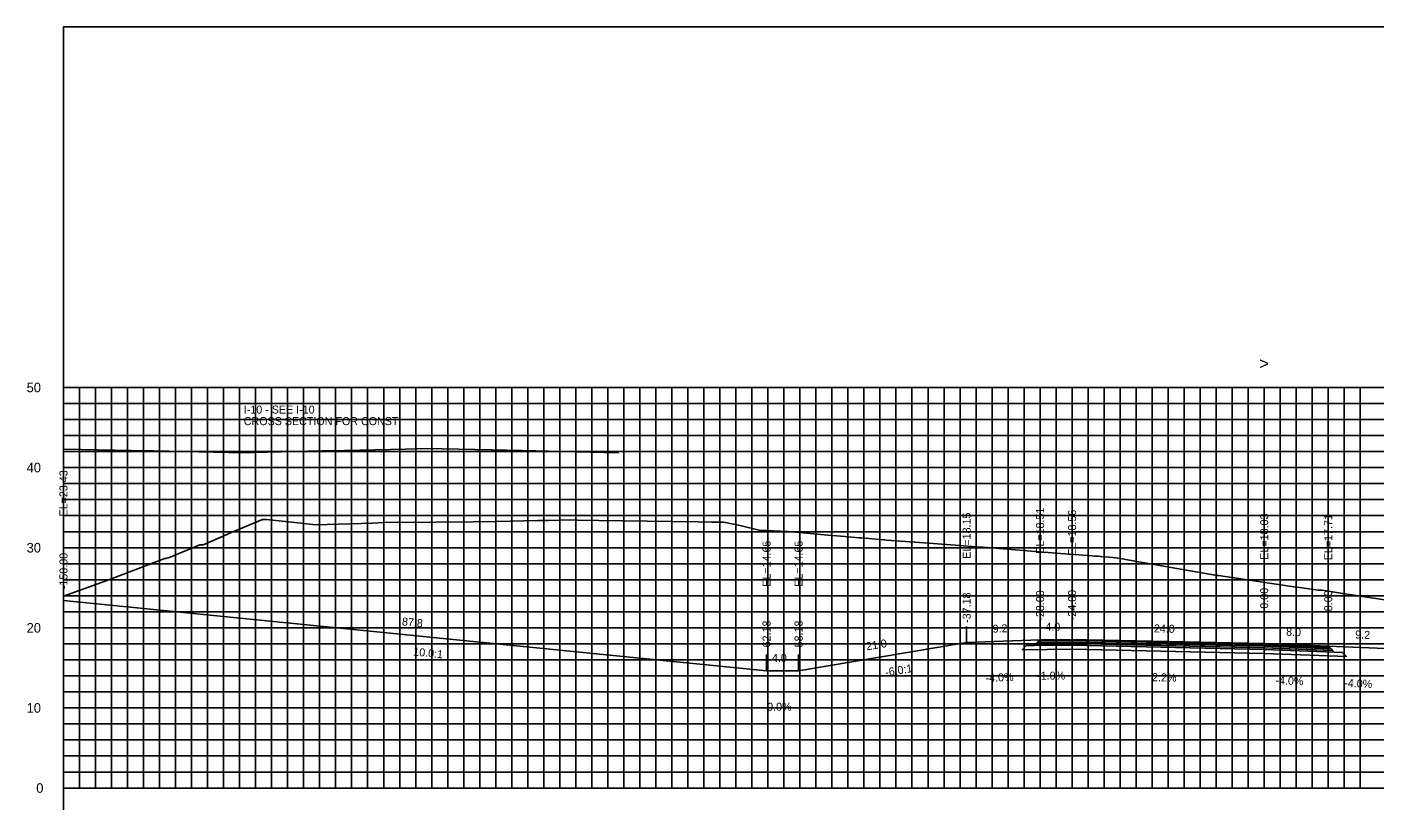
# Model space of a CAD drawing. Extents: x 1797305 to 1804485, y 245831 to 250849.
# Drawn here: x 1802476.4 to 1802644.7, y 250172.9 to 250269.4 of the extents above; entities that cross this region are included whole.
import ezdxf

# ---------------------------------------------------------------- set-up
doc = ezdxf.new("R2010")
doc.units = 0
for name, color, linetype in [('29', 7, 'Continuous'), ('60', 7, 'Continuous'), ('ALIGN-CARP', 7, 'Continuous'), ('BASE', 7, 'Continuous'), ('CL-CNST', 7, 'Continuous'), ('Level 31', 7, 'Continuous'), ('Level 62', 7, 'Continuous'), ('LIMT-CSLINE', 7, 'Continuous'), ('M-ROADS', 7, 'Continuous'), ('SURVEY - DRAINAGE - Area Shapes', 7, 'Continuous'), ('SURVEY - DRAINAGE - Bridge Hydraulic Data - Points - Locators', 7, 'Continuous')]:
    doc.layers.add(name, color=color, linetype=linetype)

msp = doc.modelspace()

# ---------------------------------------------------------------- linework, layer by layer
for p, q in [((1802481, 250197.86), (1802481, 250199.86)), ((1802593.83, 250192.58), (1802593.83, 250194.58)), ((1802603, 250192.95), (1802603, 250194.95)), ((1802607, 250192.99), (1802607, 250194.99)), ((1802631, 250192.46), (1802631, 250194.46)), ((1802639, 250192.14), (1802639, 250194.14)), ((1802568.83, 250189.08), (1802568.83, 250191.08)), ((1802572.83, 250189.08), (1802572.83, 250191.08))]:
    msp.add_line(p, q)
msp.add_lwpolyline([(1802481, 250079.43), (1802781, 250079.43), (1802781, 250269.43), (1802481, 250269.43)], close=True)
at = {"layer": '29'}
for p, q in [((1802481, 250224.43), (1802781, 250224.43)), ((1802481, 250174.43), (1802481, 250224.43)), ((1802483, 250174.43), (1802483, 250224.43)), ((1802485, 250174.43), (1802485, 250224.43)), ((1802487, 250174.43), (1802487, 250224.43)), ((1802489, 250174.43), (1802489, 250224.43)), ((1802491, 250174.43), (1802491, 250224.43)), ((1802493, 250174.43), (1802493, 250224.43)), ((1802495, 250174.43), (1802495, 250224.43)), ((1802497, 250174.43), (1802497, 250224.43)), ((1802499, 250174.43), (1802499, 250224.43)), ((1802501, 250174.43), (1802501, 250224.43)), ((1802503, 250174.43), (1802503, 250224.43)), ((1802505, 250174.43), (1802505, 250224.43)), ((1802507, 250174.43), (1802507, 250224.43)), ((1802509, 250174.43), (1802509, 250224.43)), ((1802511, 250174.43), (1802511, 250224.43)), ((1802513, 250174.43), (1802513, 250224.43)), ((1802515, 250174.43), (1802515, 250224.43)), ((1802517, 250174.43), (1802517, 250224.43)), ((1802519, 250174.43), (1802519, 250224.43)), ((1802521, 250174.43), (1802521, 250224.43)), ((1802523, 250174.43), (1802523, 250224.43)), ((1802525, 250174.43), (1802525, 250224.43)), ((1802527, 250174.43), (1802527, 250224.43)), ((1802529, 250174.43), (1802529, 250224.43)), ((1802531, 250174.43), (1802531, 250224.43)), ((1802533, 250174.43), (1802533, 250224.43)), ((1802535, 250174.43), (1802535, 250224.43)), ((1802537, 250174.43), (1802537, 250224.43)), ((1802539, 250174.43), (1802539, 250224.43)), ((1802541, 250174.43), (1802541, 250224.43)), ((1802543, 250174.43), (1802543, 250224.43)), ((1802545, 250174.43), (1802545, 250224.43)), ((1802547, 250174.43), (1802547, 250224.43)), ((1802549, 250174.43), (1802549, 250224.43)), ((1802551, 250174.43), (1802551, 250224.43)), ((1802553, 250174.43), (1802553, 250224.43)), ((1802555, 250174.43), (1802555, 250224.43)), ((1802557, 250174.43), (1802557, 250224.43)), ((1802559, 250174.43), (1802559, 250224.43)), ((1802561, 250174.43), (1802561, 250224.43)), ((1802563, 250174.43), (1802563, 250224.43)), ((1802565, 250174.43), (1802565, 250224.43)), ((1802567, 250174.43), (1802567, 250224.43)), ((1802569, 250174.43), (1802569, 250224.43)), ((1802571, 250174.43), (1802571, 250224.43)), ((1802573, 250174.43), (1802573, 250224.43)), ((1802575, 250174.43), (1802575, 250224.43)), ((1802577, 250174.43), (1802577, 250224.43)), ((1802579, 250174.43), (1802579, 250224.43)), ((1802581, 250174.43), (1802581, 250224.43)), ((1802583, 250174.43), (1802583, 250224.43)), ((1802585, 250174.43), (1802585, 250224.43)), ((1802587, 250174.43), (1802587, 250224.43)), ((1802589, 250174.43), (1802589, 250224.43)), ((1802591, 250174.43), (1802591, 250224.43)), ((1802593, 250174.43), (1802593, 250224.43)), ((1802595, 250174.43), (1802595, 250224.43)), ((1802597, 250174.43), (1802597, 250224.43)), ((1802599, 250174.43), (1802599, 250224.43)), ((1802601, 250174.43), (1802601, 250224.43)), ((1802603, 250174.43), (1802603, 250224.43)), ((1802605, 250174.43), (1802605, 250224.43)), ((1802607, 250174.43), (1802607, 250224.43)), ((1802609, 250174.43), (1802609, 250224.43)), ((1802611, 250174.43), (1802611, 250224.43)), ((1802613, 250174.43), (1802613, 250224.43)), ((1802615, 250174.43), (1802615, 250224.43)), ((1802617, 250174.43), (1802617, 250224.43)), ((1802619, 250174.43), (1802619, 250224.43)), ((1802621, 250174.43), (1802621, 250224.43)), ((1802623, 250174.43), (1802623, 250224.43)), ((1802625, 250174.43), (1802625, 250224.43)), ((1802627, 250174.43), (1802627, 250224.43)), ((1802629, 250174.43), (1802629, 250224.43)), ((1802631, 250174.43), (1802631, 250224.43)), ((1802633, 250174.43), (1802633, 250224.43)), ((1802635, 250174.43), (1802635, 250224.43)), ((1802637, 250174.43), (1802637, 250224.43)), ((1802639, 250174.43), (1802639, 250224.43)), ((1802641, 250174.43), (1802641, 250224.43)), ((1802643, 250174.43), (1802643, 250224.43)), ((1802481, 250222.43), (1802781, 250222.43)), ((1802481, 250220.43), (1802781, 250220.43)), ((1802481, 250218.43), (1802781, 250218.43)), ((1802481, 250216.43), (1802781, 250216.43)), ((1802481, 250214.43), (1802781, 250214.43)), ((1802481, 250212.43), (1802781, 250212.43)), ((1802481, 250210.43), (1802781, 250210.43)), ((1802481, 250208.43), (1802781, 250208.43)), ((1802481, 250206.43), (1802781, 250206.43)), ((1802481, 250204.43), (1802781, 250204.43)), ((1802481, 250202.43), (1802781, 250202.43)), ((1802481, 250200.43), (1802781, 250200.43)), ((1802481, 250198.43), (1802781, 250198.43)), ((1802481, 250196.43), (1802781, 250196.43)), ((1802481, 250194.43), (1802781, 250194.43)), ((1802481, 250192.43), (1802781, 250192.43)), ((1802481, 250190.43), (1802781, 250190.43)), ((1802481, 250188.43), (1802781, 250188.43)), ((1802481, 250186.43), (1802781, 250186.43)), ((1802481, 250184.43), (1802781, 250184.43)), ((1802481, 250182.43), (1802781, 250182.43)), ((1802481, 250180.43), (1802781, 250180.43)), ((1802481, 250178.43), (1802781, 250178.43)), ((1802481, 250176.43), (1802781, 250176.43)), ((1802481, 250174.43), (1802781, 250174.43))]:
    msp.add_line(p, q, dxfattribs=at)
at = {"layer": 'ALIGN-CARP'}
msp.add_lwpolyline([(1802601.27, 250192.21), (1802602.27, 250192.22), (1802607, 250192.27), (1802631, 250191.74), (1802639.75, 250191.39), (1802640.75, 250191.35), (1802641.27, 250190.83), (1802631, 250191.24), (1802607, 250191.77), (1802600.77, 250191.7)], close=True, dxfattribs=at)
at = {"layer": 'CL-CNST'}
for points in [[(1802481, 250216.75), (1802481.12, 250216.75), (1802491.6, 250216.53), (1802492.29, 250216.51), (1802501.65, 250216.31), (1802501.67, 250216.31), (1802502.9, 250216.28), (1802502.9, 250216.28), (1802502.9, 250216.28), (1802502.91, 250216.28), (1802504.16, 250216.31), (1802504.19, 250216.31), (1802504.77, 250216.33), (1802513.27, 250216.52), (1802514.2, 250216.54), (1802523.76, 250216.75), (1802526.25, 250216.81), (1802534.42, 250216.63), (1802538.3, 250216.55), (1802545.08, 250216.41), (1802550.35, 250216.29)], [(1802481, 250197.86), (1802568.83, 250189.08), (1802572.83, 250189.08), (1802593.83, 250192.58), (1802603, 250192.95), (1802607, 250192.99), (1802631, 250192.46), (1802639, 250192.14), (1802648.18, 250191.77), (1802669.18, 250188.27), (1802673.18, 250188.27), (1802685.86, 250191.44)]]:
    msp.add_lwpolyline(points, dxfattribs=at)
at = {"layer": 'Level 31'}
for p, q in [((1802480.94, 250224.43), (1802481, 250224.43)), ((1802481, 250174.43), (1802481, 250224.43)), ((1802480.94, 250214.43), (1802481, 250214.43)), ((1802480.94, 250204.43), (1802481, 250204.43)), ((1802480.94, 250194.43), (1802481, 250194.43)), ((1802480.94, 250184.43), (1802481, 250184.43)), ((1802480.94, 250174.43), (1802481, 250174.43)), ((1802481, 250174.43), (1802781, 250174.43)), ((1802481, 250174.37), (1802481, 250174.43)), ((1802491, 250174.37), (1802491, 250174.43)), ((1802501, 250174.37), (1802501, 250174.43)), ((1802511, 250174.37), (1802511, 250174.43)), ((1802521, 250174.37), (1802521, 250174.43)), ((1802531, 250174.37), (1802531, 250174.43)), ((1802541, 250174.37), (1802541, 250174.43)), ((1802551, 250174.37), (1802551, 250174.43)), ((1802561, 250174.37), (1802561, 250174.43)), ((1802571, 250174.37), (1802571, 250174.43)), ((1802581, 250174.37), (1802581, 250174.43)), ((1802591, 250174.37), (1802591, 250174.43)), ((1802601, 250174.37), (1802601, 250174.43)), ((1802611, 250174.37), (1802611, 250174.43)), ((1802621, 250174.37), (1802621, 250174.43)), ((1802631, 250174.37), (1802631, 250174.43)), ((1802641, 250174.37), (1802641, 250174.43))]:
    msp.add_line(p, q, dxfattribs=at)
at = {"layer": 'Level 62'}
msp.add_lwpolyline([(1802639.36, 250191.79), (1802639.16, 250191.98), (1802631, 250192.31), (1802607, 250192.84), (1802602.85, 250192.79), (1802602.66, 250192.6), (1802607, 250192.65), (1802631, 250192.12)], close=True, dxfattribs=at)
at = {"layer": 'LIMT-CSLINE'}
msp.add_line((1802601, 250192.01), (1802601, 250181.18), dxfattribs=at)
at = {"layer": 'M-ROADS'}
msp.add_lwpolyline([(1802481, 250198.38), (1802486.22, 250200.27), (1802493.65, 250203.08), (1802493.78, 250203.08), (1802494.19, 250203.22), (1802494.31, 250203.26), (1802498.02, 250204.77), (1802498.44, 250204.78), (1802501.31, 250206.04), (1802501.85, 250206.29), (1802505.88, 250207.94), (1802506.24, 250207.94), (1802506.37, 250207.94), (1802509.92, 250207.56), (1802512.54, 250207.29), (1802519.59, 250207.51), (1802521.07, 250207.56), (1802527.53, 250207.61), (1802532.24, 250207.66), (1802535.06, 250207.71), (1802540.25, 250207.81), (1802541.54, 250207.83), (1802544.36, 250207.89), (1802545.21, 250207.88), (1802547.88, 250207.83), (1802556.9, 250207.7), (1802560.29, 250207.65), (1802561.96, 250207.63), (1802562.91, 250207.61), (1802562.98, 250207.6), (1802563.35, 250207.6), (1802563.5, 250207.6), (1802563.68, 250207.59), (1802565.55, 250207.19), (1802567.89, 250206.6), (1802569.7, 250206.53), (1802571.49, 250206.46), (1802574.33, 250206.2), (1802576.04, 250206.05), (1802578.59, 250205.82), (1802580.37, 250205.67), (1802580.67, 250205.65), (1802583.47, 250205.41), (1802583.59, 250205.4), (1802583.8, 250205.39), (1802588.51, 250205.04), (1802591.84, 250204.79), (1802593.43, 250204.67), (1802595.7, 250204.5), (1802595.86, 250204.49), (1802596.42, 250204.45), (1802598.89, 250204.26), (1802600.4, 250204.14), (1802605.55, 250203.72), (1802607.86, 250203.53), (1802608.9, 250203.45), (1802609.49, 250203.4), (1802609.86, 250203.37), (1802610.3, 250203.37), (1802610.57, 250203.35), (1802612.08, 250203.22), (1802613.03, 250203.09), (1802614.4, 250202.85), (1802625.09, 250200.96), (1802625.31, 250200.96), (1802635.01, 250199.52), (1802635.13, 250199.52), (1802637.73, 250199.13), (1802637.84, 250199.13), (1802638.23, 250199.13), (1802640.82, 250198.71), (1802649.88, 250197.34)], dxfattribs=at)
at = {"layer": 'SURVEY - DRAINAGE - Area Shapes'}
msp.add_lwpolyline([(1802639.16, 250191.98), (1802639, 250192.14), (1802631, 250192.46), (1802607, 250192.99), (1802603, 250192.95), (1802602.85, 250192.79), (1802607, 250192.84), (1802631, 250192.31)], close=True, dxfattribs=at)
at = {"layer": 'SURVEY - DRAINAGE - Bridge Hydraulic Data - Points - Locators'}
for points in [[(1802607, 250192.46), (1802631, 250191.93), (1802639.55, 250191.59), (1802639.75, 250191.39), (1802631, 250191.74), (1802607, 250192.27), (1802602.27, 250192.22), (1802602.47, 250192.41)], [(1802607, 250192.65), (1802631, 250192.12), (1802639.36, 250191.79), (1802639.55, 250191.59), (1802631, 250191.93), (1802607, 250192.46), (1802602.47, 250192.41), (1802602.66, 250192.6)]]:
    msp.add_lwpolyline(points, close=True, dxfattribs=at)

# ---------------------------------------------------------------- texts
for s, rotation, p in [('10.0:1', 354.2894, (1802524.66, 250190.98)), ('-6.0:1', 9.4623, (1802583.74, 250188.36))]:
    msp.add_text(s, height=1, rotation=rotation).set_placement(p)
at = {"layer": '60'}
for s, p in [('50', (1802476.4, 250223.83)), ('40', (1802476.4, 250213.83)), ('30', (1802476.4, 250203.83)), ('20', (1802476.4, 250193.83)), ('10', (1802476.4, 250183.83)), ('0', (1802477.6, 250173.83))]:
    msp.add_text(s, height=1.2, dxfattribs=at).set_placement(p)
at = {"layer": 'BASE'}
for s, rotation, p in [('87.8', 354.2894, (1802523.25, 250194.74)), ('9.2', 2.2906, (1802597.09, 250193.81)), ('4.0', 0.5988, (1802603.67, 250194.05)), ('24.0', 358.7397, (1802617.21, 250193.86)), ('8.0', 357.7094, (1802633.72, 250193.45)), ('9.2', 357.7094, (1802642.35, 250193.11)), ('21.0', 9.4623, (1802581.35, 250191.61)), ('-1.0%', 0.5988, (1802602.64, 250187.94)), ('-4.0%', 2.2906, (1802596.21, 250187.67)), ('2.2%', 358.7397, (1802616.98, 250187.77)), ('-4.0%', 357.7094, (1802632.39, 250187.4)), ('-4.0%', 357.7094, (1802640.98, 250187.06))]:
    msp.add_text(s, height=1, rotation=rotation, dxfattribs=at).set_placement(p)
for s, p in [('4.0', (1802569.5, 250190.18)), ('0.0%', (1802568.91, 250184.08))]:
    msp.add_text(s, height=1, dxfattribs=at).set_placement(p)
at = {"layer": 'Level 31'}
for s, height, p in [('>', 1.5, (1802630.39, 250226.68)), ('-', 0.0001, (1802481, 250174.43))]:
    msp.add_text(s, height=height, dxfattribs=at).set_placement(p)
at = {"layer": 'LIMT-CSLINE'}
for s, p in [('I-10 - SEE I-10', (1802503.53, 250221.17)), ('CROSS SECTION FOR CONST ', (1802503.53, 250219.73))]:
    msp.add_text(s, height=1, dxfattribs=at).set_placement(p)
for s, p in [('EL=23.43', (1802481.5, 250208.33)), ('EL=18.51', (1802603.5, 250203.67)), ('EL=18.56', (1802607.5, 250203.41)), ('EL=18.15', (1802594.33, 250203.05)), ('EL=18.03', (1802631.5, 250202.93)), ('EL=17.71', (1802639.5, 250202.86)), ('EL=14.65', (1802569.33, 250199.55)), ('EL=14.65', (1802573.33, 250199.55)), ('-150.00', (1802481.5, 250199.25)), ('-28.00', (1802603.5, 250195.32)), ('-24.00', (1802607.5, 250195.37)), ('0.00', (1802631.5, 250196.82)), ('8.00', (1802639.5, 250196.5)), ('-37.18', (1802594.33, 250195.04)), ('-62.18', (1802569.33, 250191.54)), ('-58.18', (1802573.33, 250191.54))]:
    msp.add_text(s, height=1, rotation=90, dxfattribs=at).set_placement(p)

doc.saveas('drawing.dxf')
